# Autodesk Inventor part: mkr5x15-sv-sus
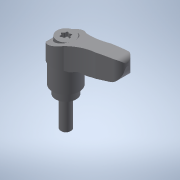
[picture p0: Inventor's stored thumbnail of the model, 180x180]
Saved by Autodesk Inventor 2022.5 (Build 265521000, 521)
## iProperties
Created: 2017-09
Part Number: mkr5x15-sv-sus
Material: 一般
Document SubType Name: Modeling
Designer: imaocorp
Density: 1 g/cm^3
Appearance: 既定
Author: imaocorp
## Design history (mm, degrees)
node "mkr5x15-sv-sus.x_t1"
node "mkr5x15-sv-sus"
node "Base1"
